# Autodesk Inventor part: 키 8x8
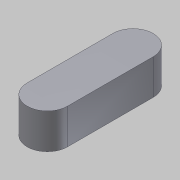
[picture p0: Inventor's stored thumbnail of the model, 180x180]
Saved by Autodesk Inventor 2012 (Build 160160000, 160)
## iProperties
Company: 한국ATC센터
Created: 2014-11
Part Number: 키 8x8
Document SubType Name: Modeling
Designer: KYOUNG IL JANG
Density: 7.86 g/cm^3
Material: 강, 연강
Mass: 10.2483 g
Surface Area: 7.8646 cm^2
Volume: 1.30386 cm^3
Author: KYOUNG IL JANG
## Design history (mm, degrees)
sketch "스케치1"
  geometry: L1 (28.264, -14)-(28.264, -31) reference; L2 (20.264, -31)-(20.264, -14) reference; A1 r 4 centre (24.264, -31) between (20.264, -31) and (28.264, -31) reference; A2 r 4 centre (24.264, -14) between (28.264, -14) and (20.264, -14) reference; 1 further point
extrude "돌출1" new body sketch "스케치1" distance "d0" = 7; taper "d1" = 0 deg
node "솔리드1"
node "참조1"
